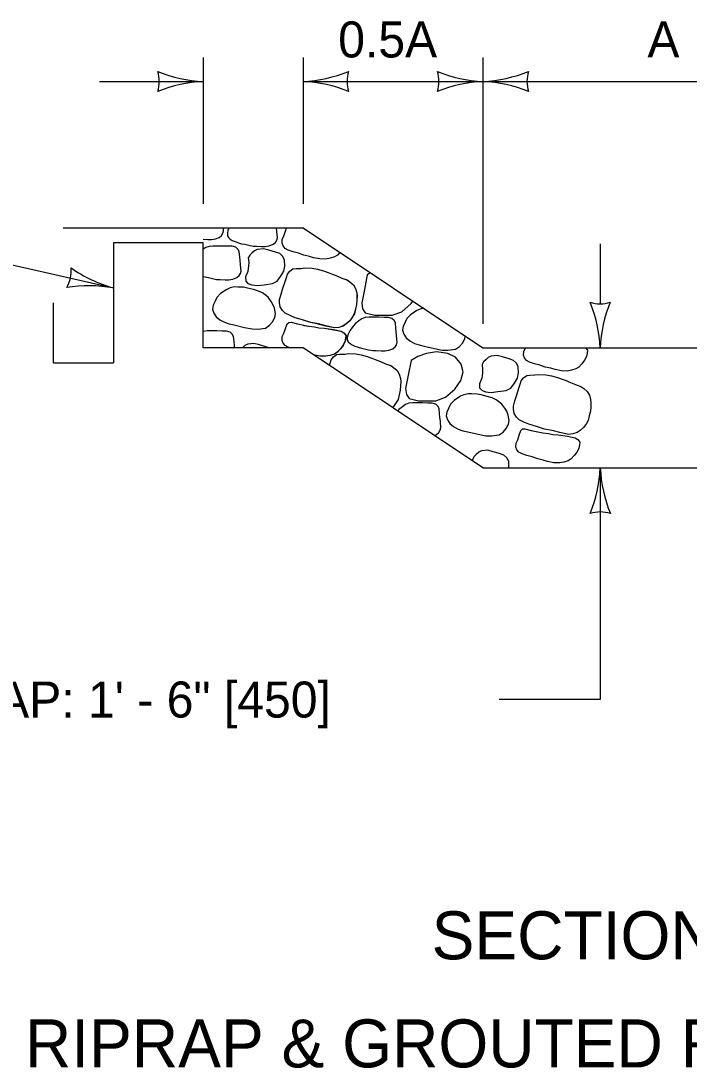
# Model space of a CAD drawing. Extents: x 49991.4 to 50021, y 49987.6 to 50011.4.
# Drawn here: x 50004.491 to 50005.605, y 49994.565 to 49996.31 of the extents above; entities that cross this region are included whole.
import ezdxf

# ---------------------------------------------------------------- set-up
doc = ezdxf.new("R2010")
doc.units = 0
for name, color, linetype in [('Level 1', 7, 'Continuous'), ('Level 2', 7, 'Continuous'), ('Level 3', 7, 'Continuous')]:
    doc.layers.add(name, color=color, linetype=linetype)

msp = doc.modelspace()

# ---------------------------------------------------------------- linework, layer by layer
at = {"layer": 'Level 1'}
for p, q in [((50004.5616, 49995.9648), (50004.9616, 49995.9648)), ((50004.9616, 49995.9648), (50005.2616, 49995.7648)), ((50004.6452, 49995.9398), (50004.6452, 49995.7398)), ((50004.5452, 49995.7398), (50004.5452, 49995.8398)), ((50004.9616, 49995.7648), (50004.7952, 49995.7648)), ((50005.2616, 49995.5648), (50004.9616, 49995.7648)), ((50005.2616, 49995.7648), (50005.8616, 49995.7648)), ((50004.5452, 49995.7398), (50004.6452, 49995.7398)), ((50005.2616, 49995.5648), (50005.8616, 49995.5648))]:
    msp.add_line(p, q, dxfattribs=at)
for points in [[(50004.7952, 49995.9458), (50004.8025, 49995.9455), (50004.8087, 49995.9455), (50004.8153, 49995.9464), (50004.8217, 49995.949), (50004.8257, 49995.9522), (50004.8279, 49995.9558), (50004.8291, 49995.9598), (50004.8286, 49995.9648)], [(50004.8384, 49995.9648), (50004.8362, 49995.9609), (50004.8355, 49995.9555), (50004.8355, 49995.9517), (50004.837, 49995.9488), (50004.8402, 49995.9463), (50004.8436, 49995.9438), (50004.8483, 49995.942), (50004.8537, 49995.9398), (50004.8591, 49995.9385), (50004.8646, 49995.9376), (50004.871, 49995.9358), (50004.8781, 49995.9344), (50004.884, 49995.9344), (50004.8924, 49995.934), (50004.8985, 49995.934), (50004.9052, 49995.9349), (50004.9116, 49995.9376), (50004.9155, 49995.9407), (50004.9177, 49995.9443), (50004.919, 49995.9483), (50004.918, 49995.9588), (50004.9174, 49995.9648)], [(50005.0229, 49995.924), (50005.0189, 49995.9195), (50005.014, 49995.9164), (50005.0066, 49995.9142), (50004.9997, 49995.9128), (50004.9898, 49995.9131), (50004.9792, 49995.9151), (50004.9721, 49995.9173), (50004.963, 49995.9195), (50004.9539, 49995.9227), (50004.9448, 49995.9249), (50004.9369, 49995.9276), (50004.9317, 49995.9305), (50004.9283, 49995.9348), (50004.9265, 49995.9393), (50004.927, 49995.9455), (50004.9297, 49995.9513), (50004.9322, 49995.9592), (50004.9342, 49995.9648)], [(50004.7952, 49995.7648), (50004.7952, 49995.9398), (50004.6452, 49995.9398)], [(50004.7952, 49995.8838), (50004.7984, 49995.883), (50004.8039, 49995.8821), (50004.8103, 49995.8803), (50004.8174, 49995.879), (50004.8233, 49995.879), (50004.8317, 49995.8785), (50004.8378, 49995.8785), (50004.8445, 49995.8794), (50004.8509, 49995.8821), (50004.8548, 49995.8853), (50004.857, 49995.8888), (50004.8583, 49995.8929), (50004.8573, 49995.9034), (50004.8565, 49995.9108), (50004.8561, 49995.9162), (50004.8551, 49995.9253), (50004.8529, 49995.9291), (50004.8494, 49995.9325), (50004.8435, 49995.9341), (50004.8364, 49995.9343), (50004.8272, 49995.9345), (50004.8181, 49995.9345), (50004.8112, 49995.9345), (50004.8048, 49995.9338), (50004.7992, 49995.932), (50004.7952, 49995.9291)], [(50004.9616, 49995.8977), (50004.9641, 49995.898), (50004.9766, 49995.8978), (50004.9857, 49995.896), (50004.9956, 49995.8933), (50005.0034, 49995.8906), (50005.0089, 49995.8884), (50005.0177, 49995.8848), (50005.0261, 49995.8812)], [(50005.0261, 49995.8812), (50005.0347, 49995.8781), (50005.0396, 49995.8747), (50005.0456, 49995.87), (50005.049, 49995.8637), (50005.051, 49995.8564), (50005.0515, 49995.8514), (50005.0512, 49995.8443), (50005.0507, 49995.8371), (50005.0488, 49995.8293), (50005.047, 49995.8216), (50005.0441, 49995.8167), (50005.0394, 49995.81), (50005.0337, 49995.8049), (50005.0286, 49995.8013), (50005.0212, 49995.799), (50005.014, 49995.7984), (50004.9995, 49995.8013), (50004.987, 49995.8046), (50004.9744, 49995.8071), (50004.9616, 49995.811)], [(50005.0743, 49995.8897), (50005.0687, 49995.8864), (50005.0639, 49995.862), (50005.0595, 49995.84), (50005.0609, 49995.8297), (50005.0654, 49995.823), (50005.0811, 49995.8194), (50005.1102, 49995.8194), (50005.1264, 49995.8252), (50005.1417, 49995.8387), (50005.1446, 49995.8429)], [(50005.1625, 49995.8309), (50005.1571, 49995.8294), (50005.1512, 49995.827), (50005.1408, 49995.82), (50005.1344, 49995.8136), (50005.132, 49995.8075), (50005.1285, 49995.8006), (50005.1275, 49995.7943), (50005.1295, 49995.7876), (50005.1335, 49995.7815), (50005.1396, 49995.7764), (50005.1472, 49995.7724), (50005.1554, 49995.7697), (50005.1635, 49995.7679), (50005.1807, 49995.7636), (50005.1938, 49995.7612), (50005.2031, 49995.7609), (50005.2157, 49995.7625), (50005.2223, 49995.7672), (50005.2273, 49995.773), (50005.2312, 49995.7802), (50005.2321, 49995.7845)], [(50004.9396, 49995.7648), (50004.9369, 49995.7658), (50004.9317, 49995.7687), (50004.9283, 49995.7729), (50004.9265, 49995.7774), (50004.927, 49995.7837), (50004.9297, 49995.7895), (50004.9322, 49995.7973), (50004.9349, 49995.805), (50004.9379, 49995.8074), (50004.9416, 49995.8079), (50004.9522, 49995.8047), (50004.963, 49995.8025), (50004.9714, 49995.8011), (50004.9807, 49995.7998), (50004.9881, 49995.7985), (50004.997, 49995.7976), (50005.013, 49995.7953), (50005.0253, 49995.7926), (50005.0297, 49995.79), (50005.0332, 49995.7855), (50005.0327, 49995.781), (50005.0314, 49995.775), (50005.0282, 49995.7689), (50005.0238, 49995.7631), (50005.0189, 49995.7577), (50005.014, 49995.7546), (50005.0066, 49995.7523), (50004.9997, 49995.751), (50004.9898, 49995.7512), (50004.9792, 49995.7532), (50004.9789, 49995.7534)], [(50004.9616, 49995.8026), (50004.9628, 49995.8024), (50004.9712, 49995.8011), (50004.9806, 49995.7997), (50004.988, 49995.7984), (50004.9968, 49995.7975), (50005.0128, 49995.7952), (50005.0251, 49995.7925), (50005.0296, 49995.7899), (50005.033, 49995.7854), (50005.0325, 49995.7809), (50005.0313, 49995.7749), (50005.0281, 49995.7688), (50005.0237, 49995.763), (50005.0187, 49995.7576), (50005.0138, 49995.7545), (50005.0064, 49995.7522), (50004.9995, 49995.7509), (50004.9897, 49995.7511), (50004.9792, 49995.7531)], [(50004.8474, 49995.7648), (50004.847, 49995.7693), (50004.8465, 49995.7747), (50004.8455, 49995.7838), (50004.8433, 49995.7876), (50004.8398, 49995.791), (50004.8339, 49995.7926), (50004.8268, 49995.7928), (50004.8177, 49995.793), (50004.8086, 49995.793), (50004.8017, 49995.793), (50004.7953, 49995.7923), (50004.7952, 49995.7923)], [(50004.9053, 49995.7648), (50004.8997, 49995.7668), (50004.8888, 49995.7699), (50004.8797, 49995.7724), (50004.8694, 49995.7712), (50004.8647, 49995.769), (50004.8605, 49995.765), (50004.8604, 49995.7648)], [(50005.4327, 49995.7648), (50005.4358, 49995.7608), (50005.4353, 49995.7563), (50005.4341, 49995.7503), (50005.4309, 49995.7442), (50005.4264, 49995.7384), (50005.4215, 49995.733), (50005.4166, 49995.7299), (50005.4092, 49995.7277), (50005.4023, 49995.7263), (50005.3925, 49995.7265), (50005.3819, 49995.7286), (50005.3747, 49995.7308), (50005.3656, 49995.733), (50005.3565, 49995.7362), (50005.3474, 49995.7384), (50005.3395, 49995.7411), (50005.3344, 49995.744), (50005.3309, 49995.7483), (50005.3292, 49995.7527), (50005.3297, 49995.759), (50005.3324, 49995.7648)], [(50005.0054, 49995.7357), (50005.0067, 49995.7394), (50005.0082, 49995.7448), (50005.0121, 49995.7499), (50005.0175, 49995.7537), (50005.0227, 49995.7544), (50005.0311, 49995.7546), (50005.037, 49995.7553), (50005.0496, 49995.7551), (50005.0587, 49995.7533), (50005.0685, 49995.7506), (50005.0764, 49995.7479), (50005.0818, 49995.7457), (50005.0907, 49995.7421), (50005.099, 49995.7385)], [(50005.099, 49995.7385), (50005.1077, 49995.7354), (50005.1126, 49995.732), (50005.1185, 49995.7273), (50005.1219, 49995.721), (50005.1239, 49995.7136), (50005.1244, 49995.7087), (50005.1242, 49995.7015), (50005.1237, 49995.6944), (50005.1217, 49995.6865), (50005.12, 49995.6789), (50005.117, 49995.674), (50005.1123, 49995.6673), (50005.1105, 49995.6656)], [(50005.4162, 49995.7036), (50005.4248, 49995.7005), (50005.4297, 49995.6971), (50005.4356, 49995.6924), (50005.4391, 49995.6861), (50005.4411, 49995.6787), (50005.4416, 49995.6738), (50005.4413, 49995.6667), (50005.4408, 49995.6595), (50005.4388, 49995.6517), (50005.4371, 49995.644), (50005.4342, 49995.6391), (50005.4295, 49995.6324), (50005.4238, 49995.6272), (50005.4187, 49995.6237), (50005.4113, 49995.6214), (50005.4041, 49995.6208), (50005.3896, 49995.6237), (50005.377, 49995.627), (50005.3645, 49995.6295), (50005.3507, 49995.6337), (50005.3381, 49995.6375), (50005.3298, 49995.6409), (50005.3219, 49995.6452), (50005.3175, 49995.6494), (50005.3135, 49995.6555), (50005.3123, 49995.6628), (50005.3123, 49995.6676), (50005.3148, 49995.6767), (50005.318, 49995.6864), (50005.3209, 49995.6962), (50005.3239, 49995.7045), (50005.3253, 49995.7099), (50005.3293, 49995.715), (50005.3347, 49995.7188), (50005.3399, 49995.7195), (50005.3482, 49995.7197), (50005.3542, 49995.7204), (50005.3667, 49995.7202), (50005.3758, 49995.7184), (50005.3857, 49995.7157), (50005.3935, 49995.713), (50005.399, 49995.7108), (50005.4078, 49995.7072), (50005.4162, 49995.7036)], [(50005.1802, 49995.6191), (50005.1842, 49995.6208), (50005.1882, 49995.6239), (50005.1904, 49995.6275), (50005.1916, 49995.6316), (50005.1906, 49995.6421), (50005.1899, 49995.6495), (50005.1894, 49995.6548), (50005.1884, 49995.664), (50005.1862, 49995.6678), (50005.1828, 49995.6712), (50005.1769, 49995.6728), (50005.1697, 49995.673), (50005.1606, 49995.6732), (50005.1515, 49995.6732), (50005.1446, 49995.6732), (50005.1382, 49995.6725), (50005.1325, 49995.6707), (50005.1274, 49995.6669), (50005.1215, 49995.662), (50005.1194, 49995.6597)], [(50005.3049, 49995.5648), (50005.305, 49995.5655), (50005.3048, 49995.5753), (50005.3016, 49995.5816), (50005.2967, 49995.5863), (50005.2895, 49995.5888), (50005.2787, 49995.5919), (50005.2696, 49995.5944), (50005.2592, 49995.5933), (50005.2545, 49995.591), (50005.2504, 49995.587), (50005.2469, 49995.5839), (50005.2442, 49995.5791), (50005.2446, 49995.5762)]]:
    msp.add_lwpolyline(points, dxfattribs=at)
for points in [[(50004.8853, 49995.929), (50004.8806, 49995.9268), (50004.8764, 49995.9228), (50004.8729, 49995.9196), (50004.8702, 49995.9149), (50004.8712, 49995.9071), (50004.8707, 49995.9015), (50004.8697, 49995.8923), (50004.8658, 49995.8831), (50004.8661, 49995.8762), (50004.8697, 49995.8724), (50004.8761, 49995.8697), (50004.8855, 49995.8686), (50004.8968, 49995.8701), (50004.9106, 49995.8719), (50004.9185, 49995.876), (50004.9242, 49995.8838), (50004.9293, 49995.8925), (50004.9311, 49995.9013), (50004.9308, 49995.9111), (50004.9276, 49995.9174), (50004.9227, 49995.9221), (50004.9155, 49995.9246), (50004.9047, 49995.9277), (50004.8956, 49995.9301)], [(50004.9499, 49995.8972), (50004.9583, 49995.8974), (50004.9642, 49995.8981), (50004.9768, 49995.8979), (50004.9859, 49995.8961), (50004.9957, 49995.8934), (50005.0036, 49995.8907), (50005.009, 49995.8885), (50005.0179, 49995.8849), (50005.0262, 49995.8813), (50005.0349, 49995.8782), (50005.0398, 49995.8748), (50005.0457, 49995.8701), (50005.0491, 49995.8638), (50005.0511, 49995.8564), (50005.0516, 49995.8515), (50005.0514, 49995.8444), (50005.0509, 49995.8372), (50005.0489, 49995.8294), (50005.0472, 49995.8217), (50005.0442, 49995.8168), (50005.0395, 49995.8101), (50005.0339, 49995.8049), (50005.0287, 49995.8014), (50005.0213, 49995.7991), (50005.0142, 49995.7985), (50004.9997, 49995.8014), (50004.9871, 49995.8047), (50004.9745, 49995.8072), (50004.9608, 49995.8114), (50004.9482, 49995.8152), (50004.9398, 49995.8186), (50004.9319, 49995.8229), (50004.9275, 49995.8271), (50004.9236, 49995.8332), (50004.9223, 49995.8405), (50004.9223, 49995.8453), (50004.9248, 49995.8544), (50004.928, 49995.8641), (50004.931, 49995.8739), (50004.9339, 49995.8822), (50004.9354, 49995.8876), (50004.9393, 49995.8927), (50004.9447, 49995.8965)], [(50004.8343, 49995.8623), (50004.824, 49995.8553), (50004.8176, 49995.8488), (50004.8151, 49995.8428), (50004.8116, 49995.8358), (50004.8107, 49995.8296), (50004.8126, 49995.8229), (50004.8166, 49995.8168), (50004.8227, 49995.8117), (50004.8304, 49995.8076), (50004.8385, 49995.8049), (50004.8466, 49995.8031), (50004.8638, 49995.7989), (50004.8769, 49995.7964), (50004.8862, 49995.7962), (50004.8988, 49995.7978), (50004.9055, 49995.8025), (50004.9104, 49995.8083), (50004.9143, 49995.8155), (50004.9156, 49995.8217), (50004.9138, 49995.8309), (50004.9114, 49995.8374), (50004.9084, 49995.8423), (50004.9035, 49995.8491), (50004.8981, 49995.8531), (50004.8939, 49995.8564), (50004.8872, 49995.8593), (50004.8791, 49995.862), (50004.869, 49995.8645), (50004.8624, 49995.8658), (50004.8528, 49995.8661), (50004.8469, 49995.8665), (50004.8402, 49995.8647)], [(50005.0653, 49995.8153), (50005.0596, 49995.8135), (50005.0544, 49995.8097), (50005.0485, 49995.8047), (50005.0436, 49995.7991), (50005.0396, 49995.7935), (50005.036, 49995.7868), (50005.0352, 49995.7814), (50005.0352, 49995.7776), (50005.0367, 49995.7747), (50005.0399, 49995.7723), (50005.0433, 49995.7698), (50005.048, 49995.768), (50005.0534, 49995.7658), (50005.0589, 49995.7644), (50005.0643, 49995.7635), (50005.0707, 49995.7617), (50005.0778, 49995.7604), (50005.0837, 49995.7604), (50005.0921, 49995.7599), (50005.0982, 49995.7599), (50005.1049, 49995.7608), (50005.1113, 49995.7635), (50005.1152, 49995.7667), (50005.1175, 49995.7702), (50005.1187, 49995.7743), (50005.1177, 49995.7848), (50005.117, 49995.7922), (50005.1165, 49995.7976), (50005.1155, 49995.8067), (50005.1133, 49995.8105), (50005.1098, 49995.8139), (50005.1039, 49995.8155), (50005.0968, 49995.8157), (50005.0877, 49995.8159), (50005.0786, 49995.8159), (50005.0717, 49995.8159)], [(50005.1417, 49995.7436), (50005.1368, 49995.7192), (50005.1324, 49995.6973), (50005.1339, 49995.687), (50005.1383, 49995.6803), (50005.1541, 49995.6767), (50005.1831, 49995.6767), (50005.1994, 49995.6825), (50005.2146, 49995.696), (50005.2245, 49995.7103), (50005.2284, 49995.7251), (50005.2255, 49995.7376), (50005.2156, 49995.7492), (50005.2033, 49995.7555), (50005.1841, 49995.7582), (50005.1674, 49995.7555), (50005.1531, 49995.7506)], [(50005.2751, 49995.751), (50005.2704, 49995.7488), (50005.2662, 49995.7448), (50005.2628, 49995.7416), (50005.2601, 49995.7369), (50005.261, 49995.7291), (50005.2606, 49995.7235), (50005.2596, 49995.7143), (50005.2556, 49995.7051), (50005.2559, 49995.6982), (50005.2596, 49995.6944), (50005.266, 49995.6917), (50005.2753, 49995.6906), (50005.2867, 49995.6921), (50005.3004, 49995.6939), (50005.3083, 49995.698), (50005.314, 49995.7058), (50005.3192, 49995.7145), (50005.3209, 49995.7233), (50005.3206, 49995.7331), (50005.3174, 49995.7394), (50005.3125, 49995.7441), (50005.3054, 49995.7466), (50005.2945, 49995.7497), (50005.2854, 49995.7522)], [(50005.2241, 49995.6843), (50005.2138, 49995.6773), (50005.2074, 49995.6708), (50005.2049, 49995.6648), (50005.2015, 49995.6578), (50005.2005, 49995.6516), (50005.2025, 49995.6449), (50005.2064, 49995.6388), (50005.2126, 49995.6337), (50005.2202, 49995.6296), (50005.2283, 49995.6269), (50005.2364, 49995.6252), (50005.2537, 49995.6209), (50005.2667, 49995.6184), (50005.2761, 49995.6182), (50005.2886, 49995.6198), (50005.2953, 49995.6245), (50005.3002, 49995.6303), (50005.3041, 49995.6375), (50005.3054, 49995.6437), (50005.3037, 49995.6529), (50005.3012, 49995.6594), (50005.2982, 49995.6643), (50005.2933, 49995.6711), (50005.2879, 49995.6751), (50005.2837, 49995.6784), (50005.2771, 49995.6814), (50005.2689, 49995.684), (50005.2588, 49995.6865), (50005.2522, 49995.6879), (50005.2426, 49995.6881), (50005.2367, 49995.6885), (50005.23, 49995.6867)], [(50005.3249, 49995.6273), (50005.3278, 49995.6297), (50005.3315, 49995.6302), (50005.3421, 49995.627), (50005.3529, 49995.6248), (50005.3613, 49995.6234), (50005.3707, 49995.6221), (50005.3781, 49995.6208), (50005.3869, 49995.6199), (50005.4029, 49995.6176), (50005.4152, 49995.6149), (50005.4197, 49995.6123), (50005.4231, 49995.6078), (50005.4226, 49995.6033), (50005.4214, 49995.5973), (50005.4182, 49995.5912), (50005.4138, 49995.5854), (50005.4088, 49995.58), (50005.4039, 49995.5769), (50005.3965, 49995.5746), (50005.3896, 49995.5733), (50005.3798, 49995.5735), (50005.3692, 49995.5755), (50005.362, 49995.5778), (50005.3529, 49995.58), (50005.3438, 49995.5831), (50005.3347, 49995.5854), (50005.3268, 49995.5881), (50005.3217, 49995.591), (50005.3182, 49995.5952), (50005.3165, 49995.5997), (50005.317, 49995.606), (50005.3197, 49995.6118), (50005.3222, 49995.6196)]]:
    msp.add_lwpolyline(points, close=True, dxfattribs=at)
at = {"layer": 'Level 3'}
for p, q in [((50004.7952, 49996.2488), (50004.7952, 49996.0048)), ((50004.9616, 49996.2488), (50004.9616, 49996.0048)), ((50005.2616, 49996.2488), (50005.2616, 49995.8048)), ((50004.6218, 49996.2088), (50004.7952, 49996.2088)), ((50004.9616, 49996.2088), (50005.2616, 49996.2088)), ((50005.2616, 49996.2088), (50005.8616, 49996.2088)), ((50004.2746, 49995.9488), (50004.6452, 49995.8648)), ((50005.4572, 49995.9383), (50005.4572, 49995.8383))]:
    msp.add_line(p, q, dxfattribs=at)
msp.add_lwpolyline([(50005.4573, 49995.5648), (50005.4573, 49995.1789), (50005.2885, 49995.1789)], dxfattribs=at)
for centre, radius, start, end in [((50004.8044, 49996.4309), 0.2223, 247.456, 267.6395), ((50004.667, 49996.2088), 0.0548, 342.1388, 17.8612), ((50004.9501, 49996.4415), 0.233, 272.8273, 292.0772), ((50005.0898, 49996.2088), 0.0548, 162.1388, 197.8612), ((50005.2708, 49996.4309), 0.2223, 247.456, 267.6395), ((50005.1334, 49996.2088), 0.0548, 342.1388, 17.8612), ((50005.2501, 49996.4415), 0.233, 272.8273, 292.0772), ((50005.3898, 49996.2088), 0.0548, 162.1388, 197.8612), ((50004.8067, 49995.9761), 0.233, 92.8273, 112.0772), ((50004.9525, 49995.9866), 0.2223, 67.456, 87.6395), ((50005.2731, 49995.9761), 0.233, 92.8273, 112.0772), ((50005.2525, 49995.9866), 0.2223, 67.456, 87.6395), ((50004.5202, 49995.8932), 0.0548, 329.3774, 5.0997), ((50004.7032, 49996.0795), 0.2223, 234.6946, 254.8781), ((50004.605, 49995.6353), 0.233, 80.0659, 99.3157), ((50005.4572, 49995.893), 0.0548, 252.1388, 287.8612), ((50005.2245, 49995.7533), 0.233, 2.8273, 22.0772), ((50005.6793, 49995.7557), 0.2223, 157.456, 177.6395), ((50005.2246, 49995.5763), 0.233, 337.9228, 357.1727), ((50005.6795, 49995.574), 0.2223, 182.3605, 202.544), ((50005.4573, 49995.4366), 0.0548, 72.1388, 107.8612)]:
    msp.add_arc(centre, radius, start, end, dxfattribs=at)

# ---------------------------------------------------------------- texts
at = {"layer": 'Level 2'}
for s, height, p in [('0.5A', 0.06, (50005.0202, 49996.2488)), ('A', 0.06, (50005.5359, 49996.2488)), ('GROUTED RIPRAP: 1\' - 6" [450]', 0.06, (50003.8361, 49995.1489)), ('SECTION A-A', 0.08, (50005.176, 49994.746)), ('RIPRAP & GROUTED RIPRAP CHUTE', 0.08, (50004.4977, 49994.5659))]:
    msp.add_text(s, height=height, dxfattribs=at).set_placement(p)

doc.saveas('drawing.dxf')
